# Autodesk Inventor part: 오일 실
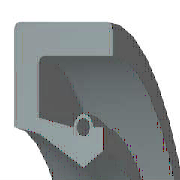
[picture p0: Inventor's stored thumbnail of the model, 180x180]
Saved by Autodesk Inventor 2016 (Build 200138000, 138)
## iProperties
IsCustomPart: 0
Created: 2016-05
Part Number: 오일 실
Material: 고무
Description: 오일-실
Document SubType Name: Modeling
Standard: KS B 2804
Designer: mduedu
Standards Organization: KS
Language: ko-KR
Size Designation: S - 17 30 8
Categories: <MemberInstance><Categories><Category DisplayName="샤프트 부품" InternalName="7f7aeb1f-a693-4053-b835-cee3144e0d98" Mnemonic="SHFT"><Category DisplayName="실링" Intern
Density: 0.93 g/cm^3
Appearance: 고무 - 검은색 - 버전 1.1
Author: mduedu
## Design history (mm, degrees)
revolve "본체" stored, may be unused: angle "d17" = 90 deg
revolve "스프링1" stored, may be unused: angle "d18" = 90 deg
body "Solid1"
sketch "스케치1"
  geometry: L1 (0, 15)-(8, 15); L2 (8, 15)-(8, 13.75); L3 (8, 13.75)-(1.75, 13.75); L4 (0, 15)-(0, 10.6); L5 (0, 10.6)-(1.75, 10.25); L6 (1.75, 10.25)-(4.9, 8.5); L7 (4.9, 8.5)-(0, 8.5); L8 (6.3, 9.375)-(6.3, 10.6); L9 (0, 0)-(9.586, 0) reference; L10 (4.9, 8.5)-(6.3, 9.375); L11 (0, 18)-(0, -3) reference; L12 (-1.917, 0)-(11.503, 0) reference; L13 (4.2, 10.6)-(1.75, 11.09); L14 (1.75, 11.09)-(1.75, 13.75); L15 (6.3, 10.6)-(5.6, 10.6); C1 r 0.455 at (4.9, 10.6); A1 r 0.7 centre (4.9, 10.6) between (5.6, 10.6) and (4.2, 10.6)
  constraints: 26 end point, 5 horizontal alignment, 4 perpendicular, 2 centre point, 2 collinear, 2 horizontal, 2 parallel, 2 point on circle, 2 point on line, 2 vertical alignment, 1 coincident
  dimensions: "d0" = 30 diameter of L1 L9 (= SD2); "d1" = 18.75 diameter of L8.start L9 (= ABDM); "d2" = 1.25 distance of L1.end L2.end (computed from SD); "d3" = 0.91 diameter of C1 (= SPDI); "d4" = 1.4 diameter of A1 (= SPDA); "d5" = 17 diameter of L6.end L9 (= NND); "d6" = 20.5 diameter of L5.end L9 (= TKDM); "d7" = 21.2 diameter of L4.end L9 (= HLDM); "d8" = 4.9 distance from line of C1.centre L4 (= SPDST); "d9" = 6.3 distance between parallel lines of L8 L4 (= SDI); "d10" = 8 distance between parallel lines of L2 L4 (= SWDT); "d12" = 1.75 distance between parallel lines of L14 L4 (= SD)
fillet "모깎기1" dims "d11" = 0.3 (= RR)
other parameters: "SD2" = 30 [user parameter; used in 1 equation term], "SWDT" = 8 [user parameter; used in 1 equation term], "RR" = 0.3 [user parameter; used in 1 equation term], "SD" = 1.75 [user parameter; used in 2 equation terms], "NND" = 17 [user parameter; used in 1 equation term], "SPDA" = 1.4 [user parameter; used in 1 equation term], "SPDI" = 0.91 [user parameter; used in 1 equation term], "TKDM" = 20.5 [user parameter; used in 1 equation term], "HLDM" = 21.2 [user parameter; used in 1 equation term], "ABDM" = 18.75 [user parameter; used in 1 equation term], "SDI" = 6.3 [user parameter; used in 1 equation term], "SPDST" = 4.9 [user parameter; used in 1 equation term], "d13" = 0, "d14" = 0, "d15" = 0, "LAB" = 0.35 [user parameter]
